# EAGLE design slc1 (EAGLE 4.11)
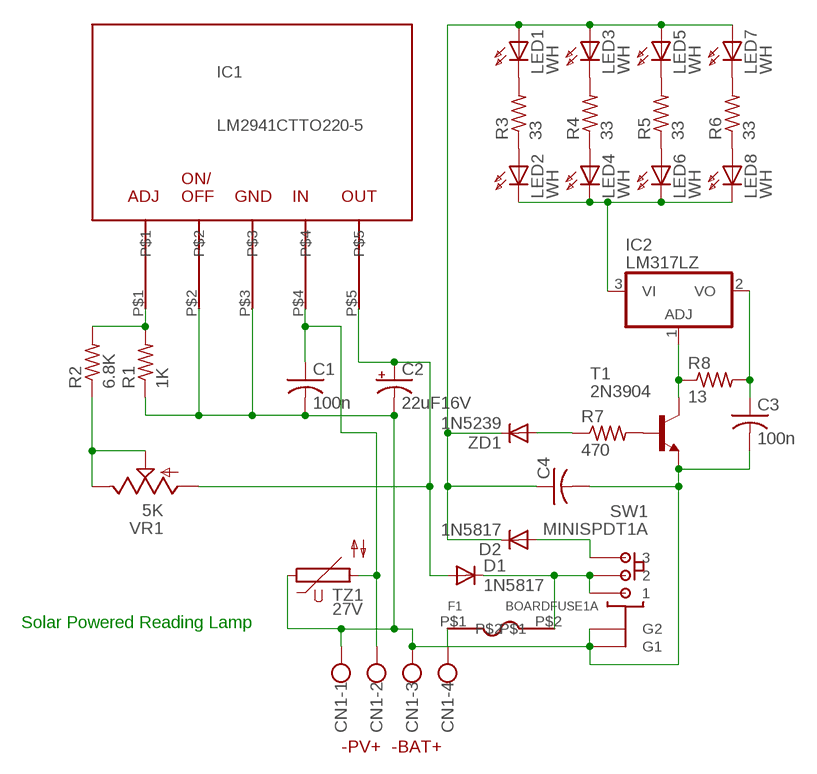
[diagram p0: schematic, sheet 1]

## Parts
C1  100n  C-US025-025X050  [C025-025X050]
C2  22uF16V  CPOL-USTT2D5  [TT2D5]
C3  100n  C-US025-025X050  [C025-025X050]
C4  C-US075-032X103  [C075-032X103]
CN1  W237-04P  [W237-4P]
D1  1N5817  1N4004  [DO41-10]
D2  1N5817  1N4004  [DO41-10]
F1  BOARDFUSE1A  [BOARDFUSE2]
IC1  LM2941CTTO220-5  [TO220-5]
IC2  LM317LZ  [TO92]
LED1  WH  LED5MM  [LED5MM]
LED2  WH  LED5MM  [LED5MM]
LED3  WH  LED5MM  [LED5MM]
LED4  WH  LED5MM  [LED5MM]
LED5  WH  LED5MM  [LED5MM]
LED6  WH  LED5MM  [LED5MM]
LED7  WH  LED5MM  [LED5MM]
LED8  WH  LED5MM  [LED5MM]
R1  1K  R-US_0204/5  [0204/5]
R2  6.8K  R-US_0204/5  [0204/5]
R3  33  R-US_0204/5  [0204/5]
R4  33  R-US_0204/5  [0204/5]
R5  33  R-US_0204/5  [0204/5]
R6  33  R-US_0204/5  [0204/5]
R7  470  R-US_0204/5  [0204/5]
R8  13  R-US_0204/5  [0204/5]
SW1  MINISPDT1A  [MINISPDT3]
T1  2N3904  [TO92]
TZ1  27V  P593  [P593]
VR1  5K  TRIM_US-S64W  [S64W]
ZD1  1N5239  1N4148  [DO35-10]

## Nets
N$1: C1.1 CN1.2 IC1.P$4 TZ1.2
N$2: CN1.4 F1.P$1
N$3: C2.+ D1.A IC1.P$5 VR1.A
N$4: C1.2 C2.- C3.2 C4.2 CN1.1 CN1.3 IC1.P$2 IC1.P$3 R1.1 SW1.G1 SW1.P$5(G2) T1.3(E) TZ1.1
N$5: R2.1 VR1.E VR1.S
N$6: IC1.P$1 R1.2 R2.2
N$7: LED8.A R6.1
N$8: LED7.K(C) R6.2
N$10: LED6.A R5.1
N$11: LED5.K(C) R5.2
N$12: LED4.A R4.1
N$13: LED3.K(C) R4.2
N$14: LED2.A R3.1
N$15: LED1.K(C) R3.2
N$17: IC2.3(VI) LED2.K(C) LED4.K(C) LED6.K(C) LED8.K(C)
N$18: D1.C F1.P$2 SW1.1 SW1.2
N$20: D2.A SW1.3
N$21: R7.1 ZD1.A
N$22: R7.2 T1.2(B)
N$23: IC2.1(ADJ) R8.1 T1.1(C)
N$24: C3.1 IC2.2(VO) R8.2
N$81: C4.1 D2.C LED1.A LED3.A LED5.A LED7.A ZD1.C

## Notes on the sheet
- Solar Powered Reading Lamp
- -PV+  -BAT+

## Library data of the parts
C1 C3 C4 = rcl:C-US: CAPACITOR, American symbol
C2 = rcl:CPOL-US: POLARIZED CAPACITOR, American symbol
CN1 = con-wago-508:W237-04P: WAGO SREW CLAMP
D1 D2 = diode:1N4004: DIODE
F1 = 01fcook:BOARDFUSE1: Printed Circuit Fuse
IC1 = 01fcook:LM2941CT: LM2941CT 5 pin TO-220
IC2 = linear:*317: Positive VOLTAGE REGULATOR
LED1-LED8 = led:LED5MM: LED
R1-R8 = rcl:R-US_: RESISTOR, American symbol
SW1 = 01fcook:MINISPDT1: mini spdt switch with side tabs
T1 = transistor:2N3904: NPN TRANSISTOR
TZ1 = varistor:P593: VARISTOR
VR1 = pot:TRIM_US-: POTENTIOMETER
ZD1 = diode:1N4148: DIODE

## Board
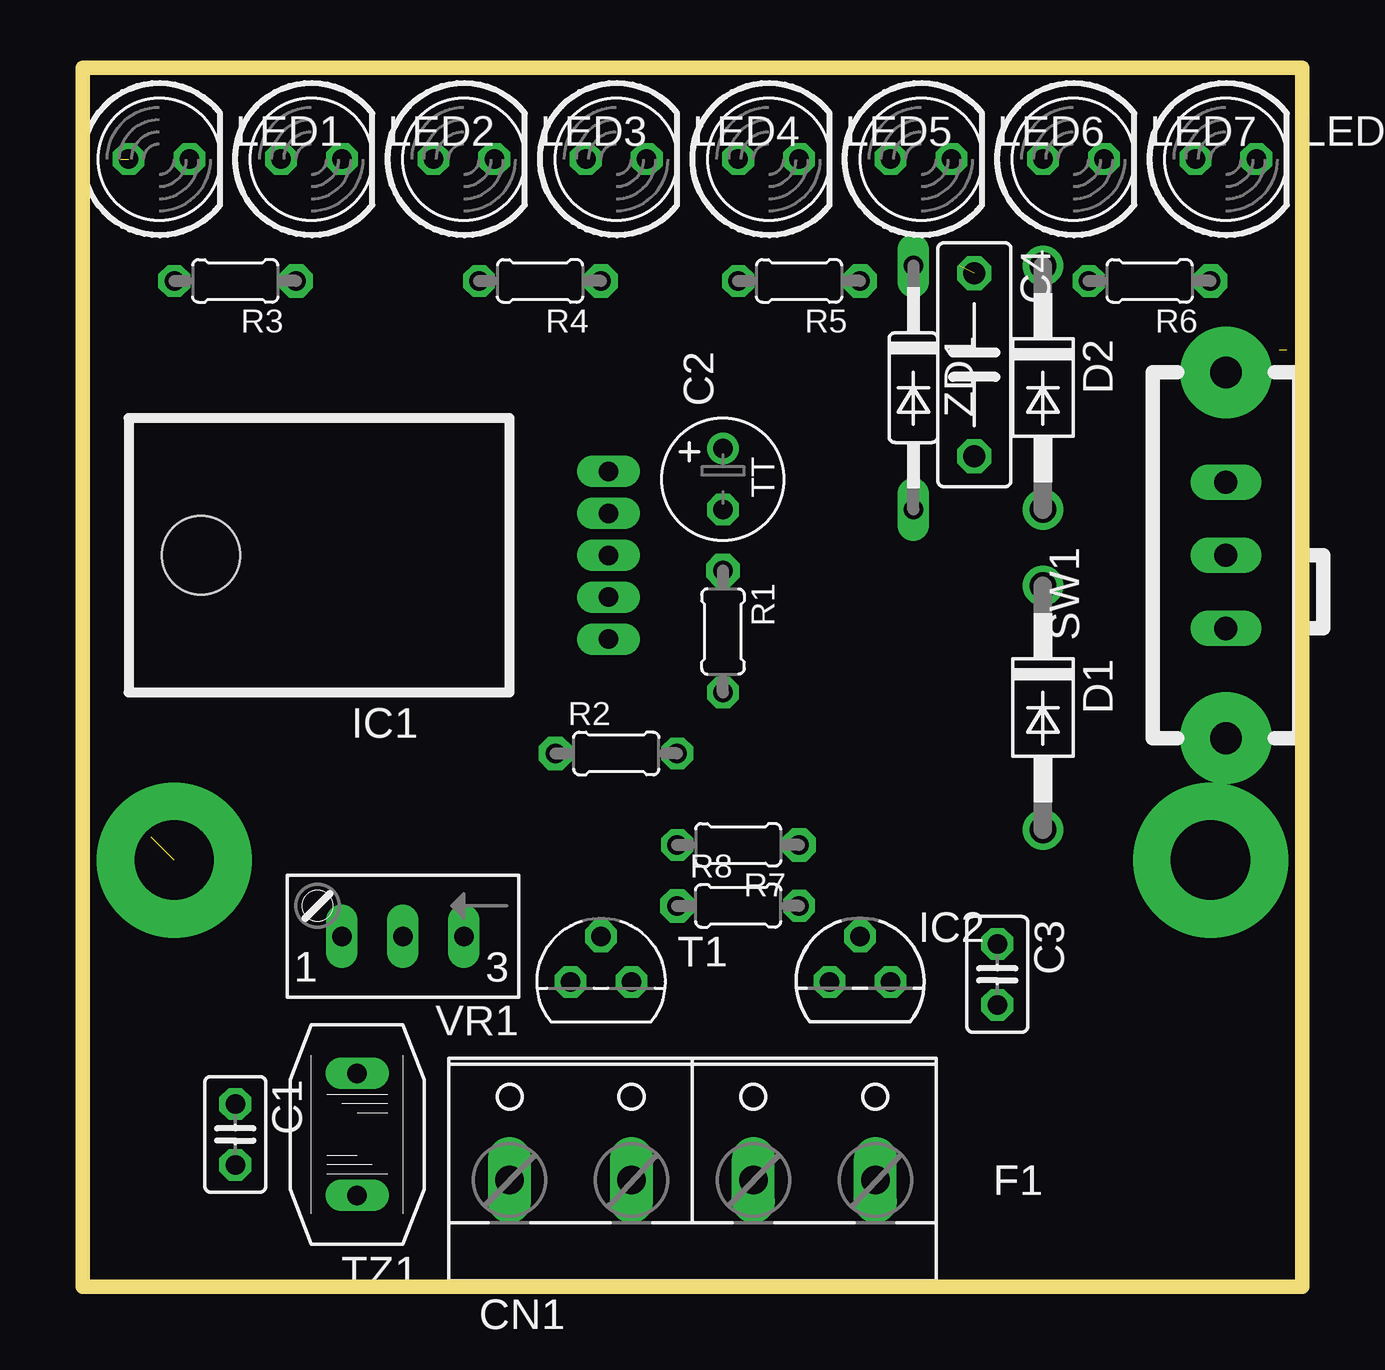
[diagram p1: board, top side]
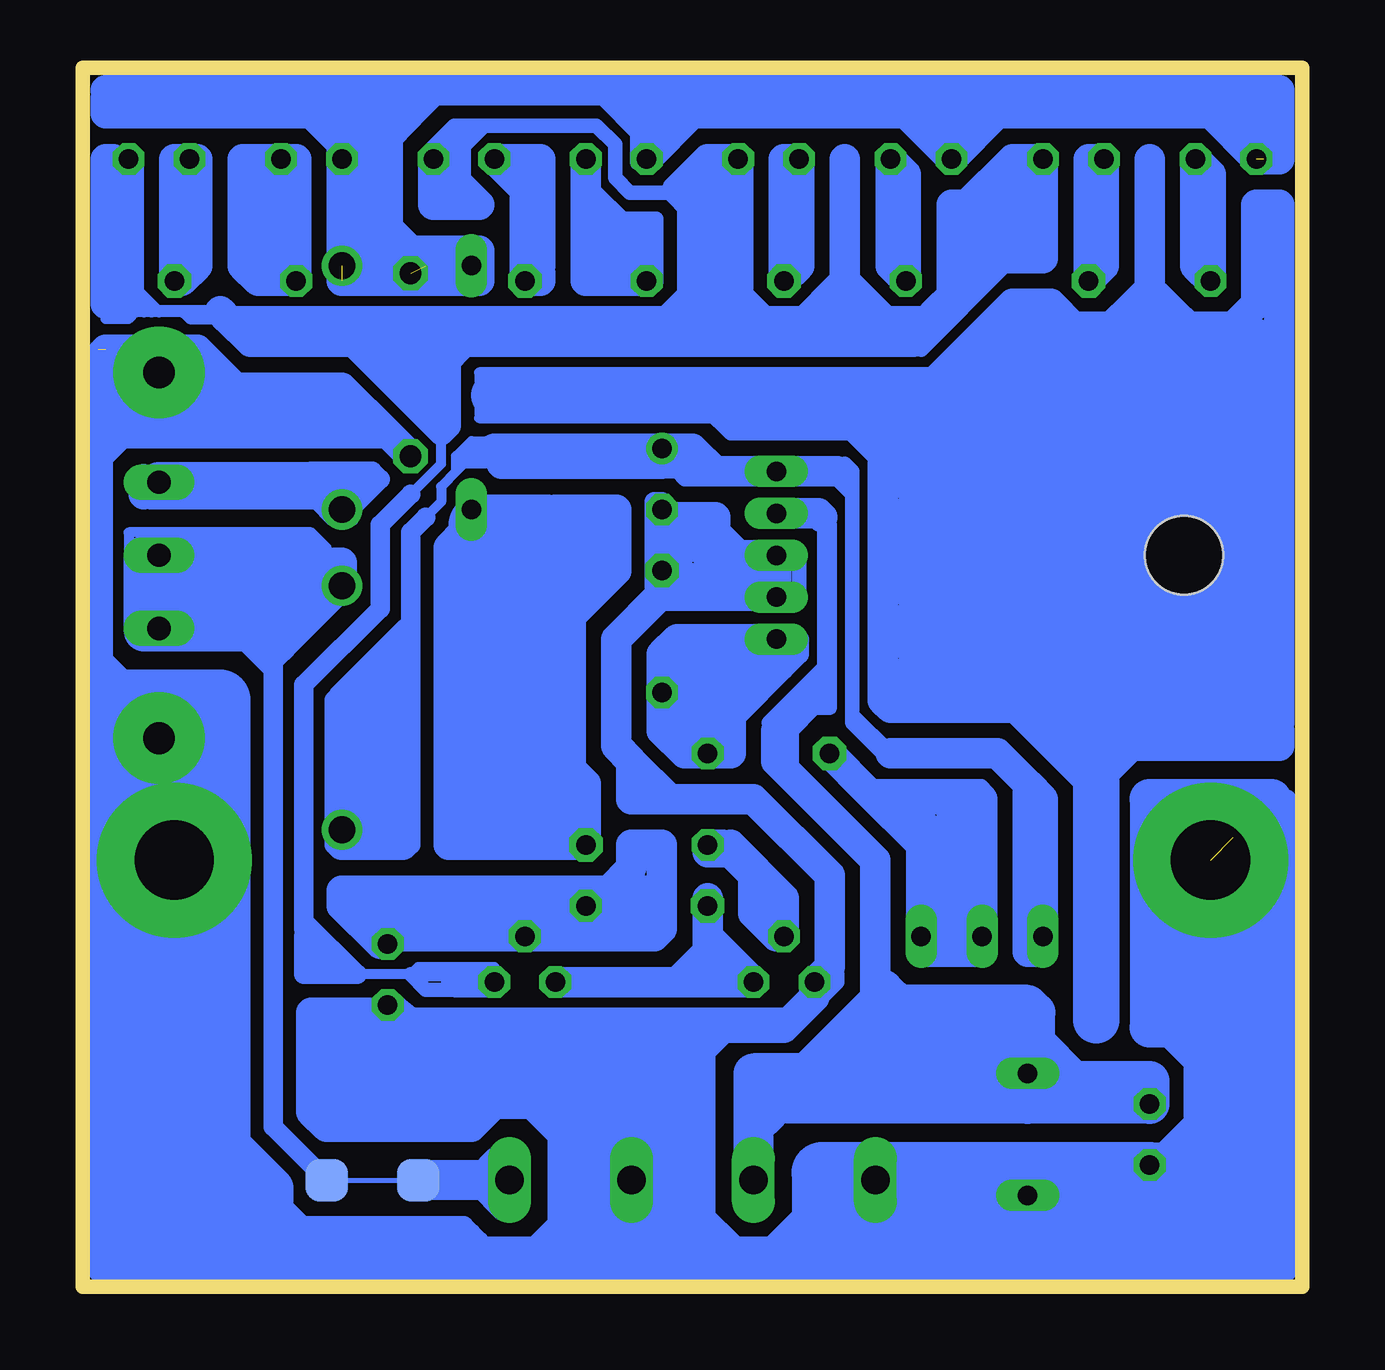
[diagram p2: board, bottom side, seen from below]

Size 50.8 x 50.8 mm. Coordinates in mm from the lower left corner, seen from the top.
Outline: 0,0 0,50.8 50.8,50.8 50.8,0 0,0
Copper layers (1*16): Top 0.035mm / dielectric 1.5mm / Bottom 0.035mm
Design rules "default": minimum track width 10mil, minimum drill 24mil, track to track 8mil, track to pad 8mil, pad to pad 8mil, via to via 8mil, smd to smd 8mil, copper to edge 40mil, drill to drill 8mil, minimum pad ring 10mil, minimum via ring 8mil, stop-mask expansion 4mil, vias tented up to drill 0mil, thermal gap 10mil

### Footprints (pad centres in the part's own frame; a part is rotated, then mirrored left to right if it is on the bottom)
C025-025X050 = drill 0.813 octagon: 1 -1.27,0; 2 1.27,0
TT2D5 = drill 0.813 round: + 1.27,0 | drill 0.813 octagon: - -1.27,0
C075-032X103 = drill 0.914 octagon: 1 -3.81,0; 2 3.81,0
W237-4P = drill 1.194 long: 1 -7.62,-0.635; 2 -2.54,-0.635; 3 2.54,-0.635; 4 7.62,-0.635
DO41-10 = drill 1.118 round: A 5.08,0; C -5.08,0
BOARDFUSE2 = smd 1.778 x 1.778 bottom: P$1 0,0; P$2 -3.81,0
TO220-5 = drill 0.813 long: P$1 -3.493,-10.477; P$2 -1.746,-10.477; P$3 0,-10.477; P$4 1.746,-10.477; P$5 3.493,-10.477 | hole 3.264: 0,6.509
TO92 = drill 0.813 octagon: 1 -1.27,0; 2 0,1.905; 3 1.27,0
LED5MM = drill 0.813 octagon: A -1.27,0; K 1.27,0
0204/5 = drill 0.813 pad 1.397 octagon: 1 -2.54,0 | drill 0.813 octagon: 2 2.54,0
MINISPDT3 = drill 0.965 long: 1 -3.048,0; 2 0,0; 3 3.048,0 | drill 1.321 pad 3.81 round: G1 -7.62,0; P$5 7.62,0
TO92' = drill 0.813 octagon: 1 1.27,0; 2 0,1.905; 3 -1.27,0
P593 = drill 0.813 long: 1 0,2.54; 2 0,-2.54
S64W = drill 0.813 long: A 2.54,1.27; E -2.54,1.27; S 0,1.27
DO35-10 = drill 0.813 long: A 5.08,0; C -5.08,0

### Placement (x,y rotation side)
C1  6.35,6.35 270 top
C2  26.67,33.66 90 top
C3  38.1,13.02 270 top
C4  37.15,38.42 270 top
CN1  25.4,5.08 0 top
D1  40.01,24.13 270 top
D2  40.01,37.47 270 top
F1  36.83,4.45 180 top
IC1  11.43,30.48 90 top
IC2  32.38,12.7 0 top
LED1  3.17,46.99 0 top
LED2  9.53,46.99 0 top
LED3  15.88,46.99 0 top
LED4  22.23,46.99 0 top
LED5  28.57,46.99 0 top
LED6  34.92,46.99 0 top
LED7  41.27,46.99 0 top
LED8  47.62,46.99 0 top
R1  26.67,27.3 270 top
R2  22.23,22.23 0 top
R3  6.35,41.91 180 top
R4  19.05,41.91 180 top
R5  29.84,41.91 180 top
R6  44.45,41.91 180 top
R7  27.3,18.41 180 top
R8  27.3,15.88 0 top
SW1  47.62,30.48 90 top
T1  2N3904  [TO92']  21.59,12.7 0 top
TZ1  11.43,6.35 180 top
VR1  13.34,15.88 180 top
ZD1  34.61,37.47 270 top

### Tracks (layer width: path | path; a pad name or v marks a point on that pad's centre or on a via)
N$1
  Bottom 0.406: 20,25.08 20,32.07
  Bottom 0.61: 20,32.07 19.68,31.75 19.68,26.35 | 19.68,25.4 19.68,26.35 | 20.32,24.77 20,25.08 19.68,25.4 | 19.68,26.35 19.68,26.04 22.23,23.5 | 19.68,25.4 19.68,24.13 20.32,24.13 21.27,23.18 21.27,21.59
  Bottom 1.27: IC1.P$4 20.16,32.23 20,32.07 | 18.41,8.89 18.41,8.57 | 20.32,24.77 21.91,23.18 21.91,21.91 17.78,17.78 17.78,9.84 17.78,8.89
  Bottom 1.676: 11.43,7.62 C1.1 6.35,8.57 8.89,8.57 | 11.43,7.62 TZ1.2 17.78,8.89 18.41,8.89 20.64,8.89 | 20.64,8.89 22.86,8.89 CN1.2 | 8.89,8.57 10.48,8.57 10.79,8.89 | 11.43,7.62 21.91,7.62 22.54,6.99 | 8.89,8.57 9.53,8.57 11.11,10.16 11.11,11.43 11.43,11.75 16.83,11.75 17.46,12.38 17.46,12.06 20.64,8.89 | 17.78,9.84 18.41,9.84
N$2
  Bottom 1.676: CN1.4 F1.P$1
N$3
  Bottom 0.406: 36.51,32.07 35.88,32.7 35.88,33.34 35.24,33.97 | 35.24,33.97 34.92,34.29 33.34,34.29 | 35.24,33.97 35.24,34.61 | 35.24,34.61 34.61,35.24 33.97,35.24 | 35.24,34.61 34.29,34.61
  Bottom 0.61: 19.37,33.97 18.73,33.34 18.73,33.02 | 17.14,22.23 18.73,23.81 | 37.15,27.62 37.15,30.8 37.15,26.67 | 18.73,23.81 18.73,23.5 17.46,22.23 | 18.73,33.02 18.73,33.97 19.05,34.29 | 18.73,23.81 18.73,33.02 | 18.73,33.02 19.37,33.66
  Bottom 0.813: 37.15,27.62 40.01,24.77 | 40.01,24.77 D1.A | 37.15,18.41 37.15,30.8 37.15,31.43 36.51,32.07 | 40.01,24.77 40.32,24.45 40.32,18.41
  Bottom 1.27: 23.81,33.97 IC1.P$5 19.37,33.97 | 23.81,33.97 24.45,33.97 25.4,34.92 C2.+ | 15.24,22.23 12.7,22.23 11.43,20.95 | 15.24,22.23 15.56,22.23 | 11.43,20.95 10.79,20.32 VR1.A | 15.24,22.23 17.14,22.23 | 10.79,13.97 11.43,13.97 11.43,20.95 | D1.A 40.01,18.41 37.47,18.41 37.47,26.99 | 23.81,33.97 25.4,33.97 26.04,34.61 | 33.34,34.29 26.67,34.29 C2.+ | C2.+ 33.66,34.92
N$4  (via drill 3.3 pad 6.45)  (2 unrouted)
  Bottom 0.61: 47.62,24.77 48.26,24.13 50.16,24.13 50.16,27.3 50.16,38.1 SW1.P$5 | 49.85,35.24 49.85,25.72
  Bottom 0.813: 50.16,32.7 50.16,39.05 | 50.16,27.3 50.16,32.7 | 50.16,27.3 50.16,0.64 0.64,0.64 0.64,20.32 | 50.16,32.7 50.16,34.29 48.9,35.56 | 50.16,27.3 50.16,26.35 48.58,24.77 | 22.07,28.73 25.56,28.73 25.72,28.89 | 26.99,28.57 25.72,28.57 | 25.72,28.57 21.27,28.57 | 25.72,28.57 25.72,28.89 | 25.72,28.89 R1.1
  Bottom 1.27: IC1.P$2 22.07,28.73 21.91,28.89 IC1.P$3 23.5,30.48 | 23.5,30.48 24.77,30.48 C2.- R1.1 | C3.2 33.02,7.62 29.21,7.62 27.94,6.35 CN1.3 | 21.59,10.79 20.32,12.06 T1.3 19.68,13.34 19.68,17.14 22.86,20.32 26.04,20.32 | 21.59,10.79 24.13,10.79 25.4,9.53 25.4,3.17 | 25.4,1.27 25.4,3.17 | 26.35,29.21 26.99,28.57 28.57,26.99 28.57,22.54 27.94,21.91 | 27.94,21.91 26.35,20.32 26.04,20.32 | 23.18,1.27 23.5,1.27 25.4,3.17 | 21.59,10.79 38.1,10.79 38.73,11.43 41.27,11.43 41.27,7.3 40.64,6.67 34.61,6.67 33.66,7.62 32.07,7.62 30.8,6.35 30.8,2.54 32.07,1.27 | 46.04,38.42 47.31,38.42 SW1.P$5 | 26.04,32.07 24.45,32.07 24.45,31.43 23.5,30.48 | 26.04,20.32 27.94,20.32 27.94,21.91 | C4.2 38.1,35.56 | 38.1,35.56 40.01,35.56 | 40.01,37.47 40.01,35.88 49.21,35.88 49.85,35.24 49.85,39.05 46.04,39.05 44.45,37.47 40.01,37.47 | 38.1,35.56 40.01,37.47
  Bottom 1.676: 17.78,1.27 23.18,1.27 25.4,1.27 27.94,1.27 | 27.94,1.27 32.07,1.27 49.53,1.27 49.53,24.77 48.58,24.77 47.62,24.77 SW1.G1 | 27.94,1.27 CN1.3 | 17.78,1.27 CN1.1 | 6.35,1.27 1.27,1.27 1.27,20.32 6.35,20.32 6.35,10.79 5.4,10.79 | 11.43,1.27 6.35,1.27 | 17.78,1.27 11.43,1.27 | C1.2 17.78,5.08 | 6.35,1.27 C1.2 | 11.43,1.27 TZ1.1 | 5.4,10.79 3.81,10.79 3.81,5.08 C1.2 | 6.35,4.76 6.03,4.76 4.13,6.67 4.13,9.53 5.4,10.79
  Bottom 2.54: 2.86,4.76 2.86,18.73 | 2.86,4.76 2.86,2.22 | 2.86,4.76 6.35,4.76 20,4.76 20,1.91
  other vias: 3.81,17.78
N$5
  Bottom 0.406: 18.1,20.64 18.1,20.95 13.34,20.95 13.02,20.64
  Bottom 1.27: VR1.S VR1.E 15.88,15.56 | 15.88,15.56 15.88,18.41 18.1,20.64 R2.1 | 15.88,15.56 13.65,15.56
N$6
  Bottom 1.27: IC1.P$1 26.04,26.99 26.67,26.35 R1.2 26.67,23.18 25.72,22.23 R2.2 23.81,22.23 23.81,23.81 21.59,26.04 25.72,26.04 25.72,23.18 24.77,23.18 24.77,25.08 23.5,25.08 24.13,24.45
N$7
  Bottom 1.27: LED8.A 46.35,42.55 R6.1 | R6.1 46.99,46.99 46.67,46.99 | R6.1 46.67,41.91 46.04,42.55 46.04,46.99
N$8
  Bottom 1.27: LED7.K 42.55,42.55 R6.2 | 42.55,41.91 42.23,41.91 | LED7.K 42.55,41.91 | LED7.K 41.91,46.99 41.91,42.23 | 42.55,41.91 43.5,41.91 44.13,42.55 44.13,46.99 42.86,46.99
N$9
  Bottom 1.27: 0.95,23.18 0.95,22.54 10.16,22.54 11.75,24.13 17.14,24.13 17.46,24.45 17.46,37.47 15.56,37.47 12.06,40.96 10.48,40.96 9.53,40.01 2.86,40.01 1.91,40.96 1.91,45.09 0.95,45.09 0.95,23.5
N$10
  Bottom 1.27: R5.1 32.38,45.72 LED6.A 31.75,46.99 31.75,42.55 R5.1 | R5.1 31.75,41.91 31.75,42.23
N$11
  Bottom 1.27: 29.84,46.67 LED5.K 29.84,44.45 29.84,41.91 R5.2
N$12
  Bottom 1.27: R4.1 20.95,42.55 LED4.A | LED4.A 21.59,46.35 | 21.59,46.35 21.59,42.23 | LED4.A 21.59,46.99 21.59,46.35
N$13
  Bottom 1.27: R4.2 17.14,42.55 LED3.K 16.51,46.35 R4.2
N$14
  Bottom 1.27: LED2.A 8.26,42.55 R3.1 8.89,46.35 | 8.89,46.35 LED2.A | LED2.A 8.89,46.99 8.89,46.35
N$15
  Bottom 1.27: 4.45,46.67 4.45,42.55 R3.2 | 4.45,46.67 LED1.K | 4.45,46.67 4.13,46.67 3.81,46.35 3.81,42.23
N$16
  Bottom 0.813: 40.96,32.7 40.32,32.07 39.69,32.07 39.69,32.38 38.42,33.66 38.73,33.97 40.01,33.97 | 40.01,33.97 39.69,33.97 | 40.01,33.97 41.27,33.97 | 40.01,33.97 39.37,33.34 40.01,33.34 40.01,33.02
N$17
  Bottom 0.406: 45.09,40.64 45.4,40.64 | 37.15,13.02 36.2,13.02 | 37.15,13.02 39.37,13.02 39.69,13.02 | 33.66,13.02 33.66,13.34 36.83,13.34 37.15,13.02 | 15.24,40.64 44.77,40.64 | 48.58,40.64 48.9,40.32 49.85,40.32 | 46.67,40.64 46.35,40.32 45.09,40.32 | 47.62,40.64 48.9,41.91 | 37.15,33.02 35.88,34.29 35.88,35.56 | 48.9,41.27 48.26,40.64 48.9,40.64 48.9,41.27
  Bottom 0.508: 45.4,40.64 46.67,40.64 47.62,40.64 47.94,40.64 | 47.94,40.64 48.26,40.64 48.58,40.64 | 47.94,40.64 48.58,41.27
  Bottom 0.61: 35.24,12.7 35.56,13.02 37.15,13.02 36.51,12.38 35.24,12.38 | 44.77,40.32 15.56,40.32 | 16.19,39.37 15.88,39.37 10.79,44.45 | 34.92,45.09 34.92,48 34.54,48.38 34.38,48.38 | 33.91,48.38 29.4,48.38 28.63,47.61 28.63,46.21 28.01,45.58 26.14,45.58 26.02,45.7 | 33.91,48.38 34.38,48.38 | 34.38,48.38 35.32,48.38 36.41,47.3 | 33.91,48.38 34.07,48.38 35,47.45
  Bottom 0.813: 41.59,15.24 41.59,14.92 39.69,13.02 40.32,13.02 | 41.59,15.24 41.59,25.08 38.42,28.26 38.42,31.75 37.15,33.02 | 40.32,13.02 41.59,13.02 41.59,14.61 | 40.32,13.02 39.37,13.02 41.59,15.24 | 34.61,39.37 35.88,38.1 36.83,39.05
  Bottom 1.016: 35.88,35.56 35.88,38.1 35.88,39.37 | 35.88,35.56 35.56,35.88 35.56,38.73 | 35.88,35.56 39.69,39.37
  Bottom 1.27: 48.9,41.27 48.9,41.91 LED8.K | LED2.K 10.79,44.45 10.79,42.86 12.7,42.86 13.02,42.55 | 23.5,39.37 16.19,39.37 | 23.5,39.37 34.61,39.37 35.88,39.37 39.69,39.37 43.81,39.37 44.77,40.32 45.09,40.64 | 23.5,39.37 LED4.K 24.77,46.99 26.04,45.72 26.02,45.7 25.4,45.09 25.4,41.27 26.67,40.01 | 35.56,46.35 34.29,45.09 35.56,45.09 | 35.56,46.35 LED6.K | 35.24,12.7 IC2.3 | 26.67,40.01 26.99,39.69 | 26.67,40.01 33.34,40.01 | 19.68,40.01 20,40.01 | 19.68,40.01 19.05,40.64 | 19.68,40.01 15.88,40.01 15.56,40.32 15.24,40.64 14.61,41.27 14.61,45.09 13.97,45.09 12.06,46.99 LED2.K | LED2.K 11.11,46.99 13.97,44.13 13.97,42.55 11.11,45.4 | LED6.K 36.2,45.09 35.56,45.09 | 34.92,45.09 35.56,45.09 | LED6.K 35.56,46.99 35.56,46.35
N$18
  Bottom 0.813: D1.C 40.01,28.89 42.86,26.04 | 42.86,25.4 42.86,26.04 | 42.86,25.4 42.86,6.67 F1.P$2 | 42.86,26.04 43.81,26.99 45.09,26.99 45.09,28.89 46.35,30.16 | 42.86,25.4 42.86,25.72 44.45,27.3
  Bottom 1.27: SW1.2 SW1.1 | D1.C 40.01,30.16 41.27,30.16
  Bottom 1.676: SW1.2 41.27,30.48 D1.C
N$19
  Bottom 1.27: 38.73,15.24 38.1,15.24 37.78,14.92
N$20
  Bottom 0.813: 41.27,33.53 41.27,33.66 D2.A
  Bottom 1.676: 41.15,33.53 41.27,33.53 SW1.3
N$21
  Bottom 1.27: 30.48,27.94 30.48,21.59 29.84,20.95 R7.1 35.56,18.41 35.56,25.72 | 30.48,27.94 30.48,31.43 31.43,32.38 ZD1.A | 28.57,32.38 28.57,29.84 30.48,27.94 | 34.92,31.75 34.92,31.43 35.56,30.8 35.56,25.72 | 35.56,25.72 28.57,32.38 | 28.57,32.38 31.11,32.38
N$22
  Bottom 1.27: 22.86,17.14 22.54,16.83 22.54,15.56 T1.2 21.59,16.19 | 21.59,16.19 21.91,16.19 22.86,17.14 | 22.86,17.14 24.13,18.41 R7.2 24.77,18.1 24.13,18.1 | 21.59,16.19 23.81,18.41 | 22.86,17.14 22.86,15.56 21.91,14.61
N$23
  Bottom 1.27: T1.1 23.18,12.7 | 23.18,12.7 23.5,12.7 24.77,13.97 | 24.77,16.19 R8.1 24.77,14.61 | 24.77,13.97 24.77,14.61 | 24.77,13.97 26.04,12.7 27.94,12.7 | 27.94,12.7 IC2.1 | 23.18,12.7 27.94,12.7 | 24.77,14.61 23.18,13.02
N$24
  Bottom 1.27: C3.1 36.2,15.88 33.34,15.88 32.38,14.92 IC2.2 31.11,15.88 R8.2 40.01,15.88 | 40.01,15.88 38.42,14.29 | 38.1,14.61 26.99,14.61 26.67,14.92 26.67,18.41 27.94,18.41 27.94,17.46 28.89,16.51 40.01,16.51 40.01,15.88
N$25  (via drill 3.3 pad 6.45)
  other vias: 46.99,17.78
N$26
  Bottom 2.54: 1.91,39.05 12.38,39.05
N$27
  Bottom 0.406: 14.29,37.47 14.29,38.1 34.29,38.1 34.29,36.2 23.81,36.2
  Bottom 2.54: 1.91,37.47 14.29,37.47
N$28
  Bottom 2.54: 1.59,36.2 16.19,36.2
N$29
  Bottom 2.54: 1.91,33.97 16.19,33.97
N$30
  Bottom 2.54: 1.91,31.75 16.19,31.75
N$31
  Bottom 2.54: 2.22,29.53 16.19,29.53
N$32
  Bottom 2.54: 1.91,27.3 16.19,27.3
N$33
  Bottom 2.54: 2.22,25.08 16.19,25.08
N$34
  Bottom 2.54: 1.91,23.81 9.53,23.81
N$35
  Bottom 2.54: 19.68,36.83 17.14,36.83 | 19.68,36.83 23.5,36.83 | 19.68,36.83 18.73,36.83 17.14,35.24
N$36
  Bottom 1.93: 23.5,37.15 33.66,37.15
N$37
  Bottom 1.93: 8.89,23.18 8.57,23.18 8.57,20.32 | 8.57,11.11 8.57,20 8.57,20.32 | 8.57,20.32 8.57,21.27 11.75,24.45 | 8.57,20.32 8.57,21.59 6.67,23.5
N$38
  Bottom 2.54: 4.76,11.75 4.76,19.37
N$39
  Bottom 2.54: 4.45,2.86 19.37,2.86
N$40
  Bottom 2.54: 49.21,24.45 45.09,24.45 45.09,4.76 41.91,1.59
N$41
  Bottom 2.54: 46.67,23.81 46.67,3.81 45.09,2.22
N$42
  Bottom 2.54: 48.26,23.5 48.26,2.86 47.62,2.22
N$43
  Bottom 1.676: 11.75,10.48 16.83,10.48
N$44
  Bottom 1.27: 29.53,29.53 29.53,32.38
N$46
  Bottom 2.54: 31.11,19.68 31.11,31.43 32.7,31.43 32.7,19.68 34.29,19.68 34.29,31.75
N$47
  Bottom 1.27: 13.34,13.97 15.56,13.97
N$48
  Bottom 1.27: 13.34,14.29 13.34,20.32 16.83,20.32 | 16.83,20.32 17.14,20.32 | 16.83,20.32 15.56,19.05 15.56,16.19 14.61,16.19 14.61,19.68
N$49
  Bottom 1.27: 27.3,15.56 31.75,15.56
N$50
  Bottom 1.27: 20.32,3.49 20.32,3.17 21.91,1.59
N$51
  Bottom 1.27: 25.08,2.22 25.08,10.48 24.77,10.79
N$52
  Bottom 1.27: 30.16,1.91 30.16,10.16
N$53
  Bottom 1.27: 29.21,1.91 29.21,10.16
N$54
  Bottom 2.54: 27.3,2.86 26.99,2.86 26.99,9.21 26.35,9.84 40.32,9.84
N$55
  Bottom 2.54: 27.62,8.26 40.32,8.26
N$56
  Bottom 0.61: 27.69,46.83 27.69,48.07 29.09,49.47
N$57
  Bottom 1.27: 40.64,36.51 48.9,36.51 49.21,36.83
N$58
  Bottom 1.27: 44.77,37.47 48.9,37.47
N$59
  Bottom 1.27: 26.99,16.51 27.94,16.51
N$60
  Bottom 1.27: 40.96,29.53 45.09,29.53
N$61
  Bottom 1.27: 40.96,28.89 44.45,28.89
N$62
  Bottom 1.27: 41.59,28.26 44.45,28.26
N$63
  Bottom 1.27: 41.91,27.62 44.45,27.62
N$64
  Bottom 1.27: 42.55,26.67 43.18,26.67
N$65
  Bottom 1.27: 40.96,33.02 47.94,33.02
N$66
  Bottom 1.27: 46.04,29.53 45.4,29.53 | 47.62,29.53 46.04,29.53 | 47.62,29.53 47.62,29.84 48.26,30.48 | 47.62,29.53 48.26,30.16 | 46.04,29.53 44.45,27.94
  Bottom 1.676: 47.94,30.48 48.26,30.48 48.26,27.3 43.81,27.3
N$67
  Bottom 1.27: 37.78,26.04 39.37,24.45 39.37,19.05 38.42,19.05 38.42,24.77
N$68
  Bottom 0.61: 12.38,42.55 15.88,39.05
N$69
  Bottom 1.27: 22.54,29.53 26.04,29.53 26.04,30.48
N$71
  Bottom 0.813: 41.27,13.97 40.64,13.34
N$72
  Bottom 0.813: 43.18,2.22 34.61,2.22 34.29,1.91 | 34.29,1.91 33.97,1.59 | 43.18,2.54 34.92,2.54 34.29,1.91
N$73
  Bottom 0.406: 34.29,34.92 34.61,34.92
N$74
  Bottom 1.27: 24.13,46.67 24.13,40.01 25.4,40.01 25.4,40.32 24.77,40.96
N$75
  Bottom 1.27: 24.77,45.72 24.77,46.35
N$76
  Bottom 1.27: 23.81,42.23 23.81,41.59 22.23,40.01 20.95,40.01 19.05,41.91 | 19.05,41.91 19.05,46.99 | 16.83,39.69 19.05,41.91
N$77
  Bottom 1.27: 4.13,39.37 6.03,41.27
N$78
  Bottom 1.27: 17.46,40.01 18.1,40.64
N$79
  Bottom 1.27: 6.35,41.59 6.35,41.27 | 6.35,41.59 6.35,46.99 | 8.57,39.37 6.35,41.59
N$80
  Bottom 1.676: 36.2,36.83 38.1,38.73
N$81  (3 unrouted)
  Bottom 1.27: 36.2,41.91 40.01,41.91 40.01,47.31 | 36.25,42.01 36.25,41.96 36.2,41.91 | 36.2,41.91 34.29,41.91 34.29,43.18 37.15,43.18 | 38.1,48.9 LED7.A 40.01,47.31 | LED1.A 3.81,48.9 12.7,48.9 LED3.A 16.51,48.9 25.4,48.9 LED5.A | ZD1.C 36.51,42.55 37.15,43.18 | 37.15,43.18 38.1,44.13 38.1,47.62 38.1,47.94 | 38.1,47.94 37.47,48.58 | 40.01,47.31 40.01,47.62 41.27,48.9 49.85,48.9 49.85,49.53 | 37.15,43.18 35.88,43.18 | 37.15,43.18 40.01,43.18 39.05,44.13 | 39.05,44.13 39.05,43.18 38.1,43.18 | 39.05,44.13 39.05,47.31 | 36.2,49.85 0.95,49.85 0.95,46.99 1.59,46.99 | 36.2,49.85 49.85,49.85 | 36.2,49.85 38.1,47.94
N$82
  Bottom 1.27: 43.18,42.55 43.18,46.67
N$83
  Bottom 1.27: 49.21,40.96 49.85,40.96 49.85,46.99 49.53,46.99
N$85
  Bottom 1.27: 1.59,49.21 2.86,49.21
N$86
  Bottom 1.27: 2.22,48.26 1.59,48.26
N$87
  Bottom 1.27: 13.34,49.21 15.88,49.21
N$88
  Bottom 1.27: 14.92,48.26 13.97,48.26
N$89
  Bottom 1.27: 25.72,49.21 27.79,49.21
N$90
  Bottom 1.27: 27.31,48.26 26.67,48.26
N$91
  Bottom 1.27: 40.32,48.9 38.73,48.9 | 40.32,48.9 40.32,49.21 | 39.69,48.26 40.32,48.9
N$92
  Bottom 0.61: 25.4,33.66 25.72,33.66 26.04,33.97 27.3,33.97
N$93
  Bottom 0.61: 26.67,34.29 27.3,34.29
N$94
  Bottom 0.61: 20,12.06 19.37,12.7 19.37,13.02
N$95
  Bottom 0.61: 20.95,28.89 20.95,30.16
N$96
  Bottom 1.676: 45.72,28.57 47.31,28.57
N$97
  Bottom 1.27: 46.99,33.34 47.94,33.34 48.26,33.02 48.26,33.66
N$99
  Bottom 0.406: 40.32,24.77 37.47,27.62
N$100
  Bottom 0.61: 49.53,35.24 40.01,35.24 39.69,35.56
N$101
  Bottom 0.406: 48.9,30.48 48.9,31.43 41.27,31.43 40.64,30.8
N$102
  Bottom 0.406: 21.59,11.43 37.78,11.43
N$103
  Bottom 0.61: 13.34,42.23 13.65,42.23 14.29,41.59
N$104
  Bottom 0.61: 24.77,36.51 23.81,35.56 18.41,35.56
N$105
  Bottom 1.676: 42.86,3.17 42.86,4.13 44.77,6.03
N$106
  Bottom 0.813: 33.34,3.17 34.29,4.13
N$107
  Bottom 0.813: 34.29,4.76 33.66,5.4
N$108
  Bottom 0.813: 28.57,27.3 26.99,28.89 26.99,32.7 26.67,32.7
N$109
  Bottom 0.813: 21.59,25.72 20.95,26.35 20.95,26.99
N$110
  Bottom 0.61: 35.56,40.01 44.13,40.01
N$112
  Bottom 0.61: 35.32,48.07 35.32,47.61 35.47,47.61
N$113
  Bottom 0.61: 27.07,41.85 26.91,41.85 26.91,44.49 28.32,44.49 29.4,45.58
N$114
  Bottom 1.27: 27.38,44.03 28.94,44.03 29.4,44.49
N$115
  Bottom 1.27: 27.38,42.94 29.09,42.94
